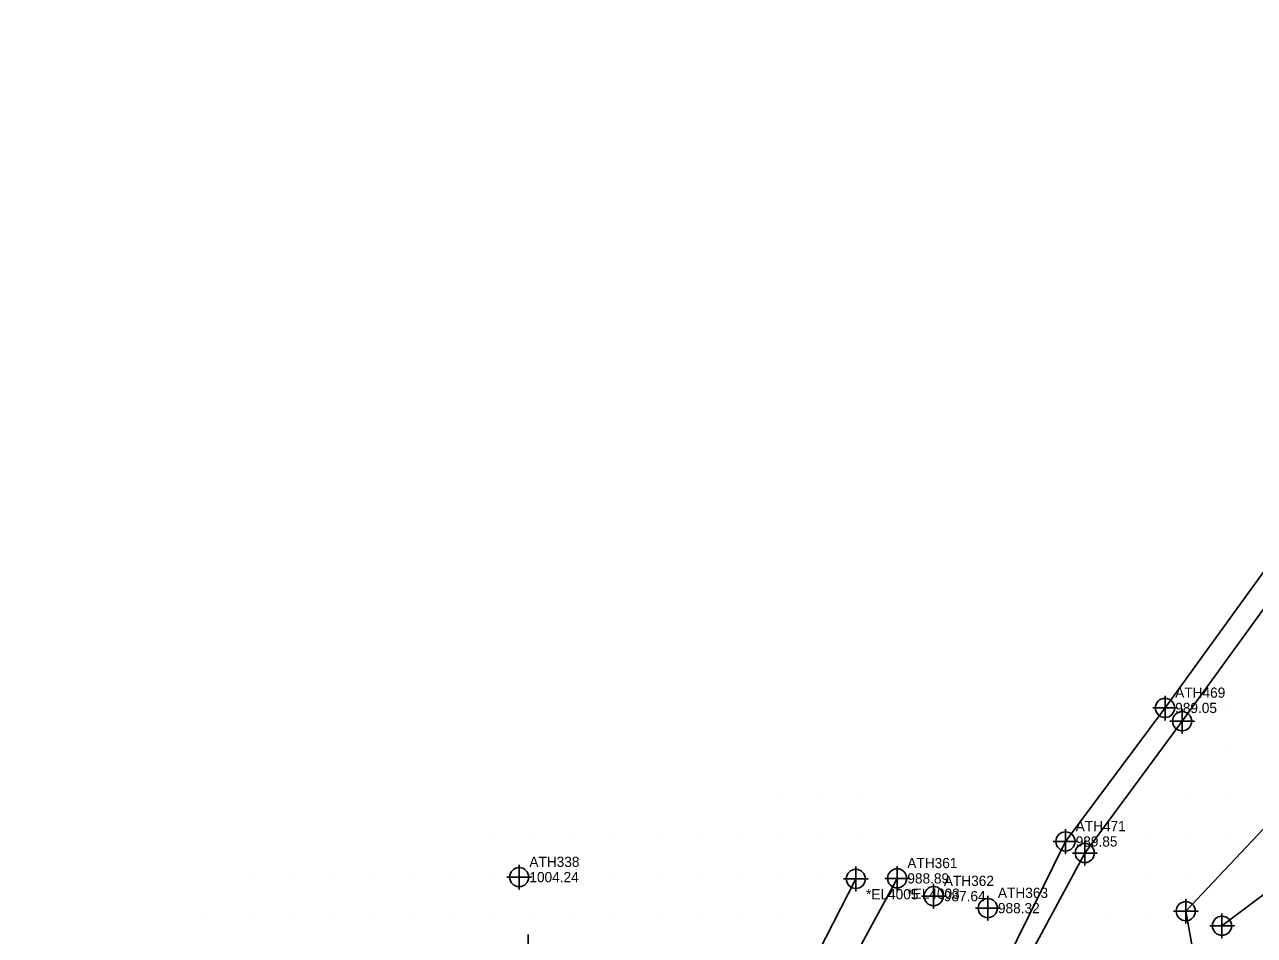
# Model space of a CAD drawing. Extents: x 1116680 to 1117499, y 661040 to 661703.
# Drawn here: x 1116885.3 to 1117186.4, y 661475 to 661698 of the extents above; entities that cross this region are included whole.
import ezdxf

# ---------------------------------------------------------------- set-up
doc = ezdxf.new("R2010")
doc.units = 0
for name, color, linetype in [('Exist DTM Breakline', 7, 'Continuous'), ('Exist DTM Breakline Cogo Comment', 7, 'Continuous'), ('Exist DTM Breakline Cogo Point CELL', 7, 'Continuous'), ('Exist DTM Crownline', 7, 'Continuous'), ('Exist DTM Drainline Cogo Comment', 7, 'Continuous'), ('Exist DTM Drainline Cogo Elevation', 7, 'Continuous'), ('Exist DTM Drainline Cogo Number', 7, 'Continuous'), ('Exist DTM Drainline Cogo Point CELL', 7, 'Continuous'), ('Exist DTM QL2 LIDAR Elevation Point', 7, 'Continuous'), ('Exist DTM Regular Point CELL', 7, 'Continuous'), ('Exist DTM Regular Point Cogo Elevation', 7, 'Continuous'), ('Exist DTM Regular Point Cogo Number', 7, 'Continuous'), ('Exist DTM Regular Point Underwater CELL', 7, 'Continuous'), ('Exist DTM Regular Point Underwater Cogo Elevation', 7, 'Continuous'), ('Exist DTM Regular Point Underwater Cogo Number', 7, 'Continuous'), ('Exist Hydro Stream or Body of Water', 7, 'Continuous'), ('Exist Roads EOP', 7, 'Continuous')]:
    doc.layers.add(name, color=color, linetype=linetype)

msp = doc.modelspace()

# ---------------------------------------------------------------- linework, layer by layer
at = {"layer": 'Exist DTM Breakline'}
for points in [[(1117128.128, 661464.169), (1117144.878, 661495.181), (1117168.704, 661527.446), (1117200.502, 661571.22), (1117217.144, 661612.812), (1117257.559, 661667.144), (1117273.855, 661694.87)], [(1117194.27, 661465.73), (1117171.77, 661469.09), (1117169.6, 661480.945), (1117189.888, 661502.41), (1117205.863, 661515.329), (1117217.572, 661523.34), (1117225.692, 661514.312), (1117221.27, 661493.665), (1117211.404, 661481.256)], [(1117178.472, 661477.376), (1117196.976, 661491.194), (1117215.079, 661507.353)], [(1117038.555, 661379.021), (1117059.605, 661420.588), (1117070.329, 661452.789), (1117088.813, 661488.846)]]:
    msp.add_lwpolyline(points, dxfattribs=at)
at = {"layer": 'Exist DTM Breakline Cogo Point CELL'}
for points in [[(1117168.704, 661530.446), (1117168.704, 661524.446), (1117168.704, 661527.446), (1117171.704, 661527.446), (1117165.704, 661527.446)], [(1117144.878, 661498.181), (1117144.878, 661492.181), (1117144.878, 661495.181), (1117147.878, 661495.181), (1117141.878, 661495.181)], [(1117088.813, 661491.846), (1117088.813, 661485.846), (1117088.813, 661488.846), (1117091.813, 661488.846), (1117085.813, 661488.846)], [(1117169.6, 661483.945), (1117169.6, 661477.945), (1117169.6, 661480.945), (1117172.6, 661480.945), (1117166.6, 661480.945)], [(1117178.472, 661480.376), (1117178.472, 661474.376), (1117178.472, 661477.376), (1117181.472, 661477.376), (1117175.472, 661477.376)], [(1117008.611, 661475.228), (1117008.611, 661469.228), (1117008.611, 661472.228), (1117011.611, 661472.228), (1117005.611, 661472.228)]]:
    msp.add_lwpolyline(points, dxfattribs=at)
for centre in [(1117168.704, 661527.446), (1117144.878, 661495.181), (1117088.813, 661488.846), (1117169.6, 661480.945), (1117178.472, 661477.376)]:
    msp.add_circle(centre, 2.344, dxfattribs=at)
at = {"layer": 'Exist DTM Crownline'}
msp.add_spline([(1117128.608, 661382.881), (1117161.083, 661393.544), (1117193.928, 661410.345), (1117229.679, 661438.384), (1117257.918, 661472.931), (1117285.234, 661525.056), (1117305.735, 661573.245), (1117329.129, 661633.315)], degree=3, dxfattribs=at)
at = {"layer": 'Exist DTM Drainline Cogo Point CELL'}
for points in [[(1117164.523, 661533.702), (1117164.523, 661527.702), (1117164.523, 661530.702), (1117167.523, 661530.702), (1117161.523, 661530.702)], [(1117140.152, 661501.019), (1117140.152, 661495.019), (1117140.152, 661498.019), (1117143.152, 661498.019), (1117137.152, 661498.019)], [(1117098.924, 661491.98), (1117098.924, 661485.98), (1117098.924, 661488.98), (1117101.924, 661488.98), (1117095.924, 661488.98)]]:
    msp.add_lwpolyline(points, dxfattribs=at)
for centre in [(1117164.523, 661530.702), (1117140.152, 661498.019), (1117098.924, 661488.98)]:
    msp.add_circle(centre, 2.344, dxfattribs=at)
at = {"layer": 'Exist DTM QL2 LIDAR Elevation Point'}
for p, q in [((1117180, 661530), (1117180, 661530)), ((1117180, 661520), (1117180, 661520)), ((1117070, 661510), (1117070, 661510)), ((1117080, 661510), (1117080, 661510)), ((1117090, 661510), (1117090, 661510)), ((1117170, 661510), (1117170, 661510)), ((1117180, 661510), (1117180, 661510)), ((1117000, 661500), (1117000, 661500)), ((1117010, 661500), (1117010, 661500)), ((1117020, 661500), (1117020, 661500)), ((1117030, 661500), (1117030, 661500)), ((1117040, 661500), (1117040, 661500)), ((1117050, 661500), (1117050, 661500)), ((1117060, 661500), (1117060, 661500)), ((1117070, 661500), (1117070, 661500)), ((1117080, 661500), (1117080, 661500)), ((1117090, 661500), (1117090, 661500)), ((1117160, 661500), (1117160, 661500)), ((1117170, 661500), (1117170, 661500)), ((1117180, 661500), (1117180, 661500)), ((1116940, 661490), (1116940, 661490)), ((1116950, 661490), (1116950, 661490)), ((1116960, 661490), (1116960, 661490)), ((1116970, 661490), (1116970, 661490)), ((1116980, 661490), (1116980, 661490)), ((1116990, 661490), (1116990, 661490)), ((1117000, 661490), (1117000, 661490)), ((1117010, 661490), (1117010, 661490)), ((1117020, 661490), (1117020, 661490)), ((1117030, 661490), (1117030, 661490)), ((1117040, 661490), (1117040, 661490)), ((1117050, 661490), (1117050, 661490)), ((1117060, 661490), (1117060, 661490)), ((1117070, 661490), (1117070, 661490)), ((1117080, 661490), (1117080, 661490)), ((1117160, 661490), (1117160, 661490)), ((1117170, 661490), (1117170, 661490)), ((1116930, 661480), (1116930, 661480)), ((1116940, 661480), (1116940, 661480)), ((1116950, 661480), (1116950, 661480)), ((1116960, 661480), (1116960, 661480)), ((1116970, 661480), (1116970, 661480)), ((1116980, 661480), (1116980, 661480)), ((1116990, 661480), (1116990, 661480)), ((1117000, 661480), (1117000, 661480)), ((1117010, 661480), (1117010, 661480)), ((1117020, 661480), (1117020, 661480)), ((1117030, 661480), (1117030, 661480)), ((1117040, 661480), (1117040, 661480)), ((1117050, 661480), (1117050, 661480)), ((1117060, 661480), (1117060, 661480)), ((1117070, 661480), (1117070, 661480)), ((1117150, 661480), (1117150, 661480)), ((1117160, 661480), (1117160, 661480))]:
    msp.add_line(p, q, dxfattribs=at)
at = {"layer": 'Exist DTM Regular Point CELL'}
msp.add_lwpolyline([(1117006.371, 661492.281), (1117006.371, 661486.281), (1117006.371, 661489.281), (1117009.371, 661489.281), (1117003.371, 661489.281)], dxfattribs=at)
msp.add_circle((1117006.371, 661489.281), 2.344, dxfattribs=at)
at = {"layer": 'Exist DTM Regular Point Underwater CELL'}
for points in [[(1117107.864, 661487.626), (1117107.864, 661481.626), (1117107.864, 661484.626), (1117110.864, 661484.626), (1117104.864, 661484.626)], [(1117121.112, 661484.694), (1117121.112, 661478.694), (1117121.112, 661481.694), (1117124.112, 661481.694), (1117118.112, 661481.694)]]:
    msp.add_lwpolyline(points, dxfattribs=at)
for centre in [(1117107.864, 661484.626), (1117121.112, 661481.694)]:
    msp.add_circle(centre, 2.344, dxfattribs=at)
at = {"layer": 'Exist Hydro Stream or Body of Water'}
for points in [[(1117125.362, 661468.034), (1117140.152, 661498.019), (1117164.523, 661530.702), (1117196.253, 661574.433), (1117208.146, 661610.151), (1117250.567, 661671.867), (1117271.101, 661697.995)], [(1116885.259, 661065.084), (1116909.522, 661128.826), (1116941.429, 661187.261), (1116973.299, 661231.015), (1117008.806, 661288.675), (1117028.625, 661329.39), (1117037.259, 661346.044), (1117054.084, 661350.959), (1117065.864, 661380.085), (1117058.435, 661381.413), (1117066.561, 661417.266), (1117077.352, 661449.252), (1117098.924, 661488.98)]]:
    msp.add_lwpolyline(points, dxfattribs=at)
at = {"layer": 'Exist Roads EOP'}
for points in [[(1117102.286, 661387.333), (1117126.621, 661394.057), (1117156.418, 661404.979), (1117187.204, 661421.689), (1117219.891, 661448.41), (1117247.012, 661480.823), (1117275.546, 661531.18), (1117296.661, 661577.27), (1117320.803, 661635.676)], [(1117131.334, 661372.856), (1117166.321, 661382.847), (1117200.815, 661399.841), (1117238.067, 661430.322), (1117267.048, 661465.689), (1117295.472, 661519.132), (1117314.821, 661568.418)]]:
    msp.add_spline(points, degree=3, dxfattribs=at)

# ---------------------------------------------------------------- texts
at = {"layer": 'Exist DTM Breakline Cogo Comment'}
msp.add_text('*EL4005', height=2.5, dxfattribs=at).set_placement((1117091.313, 661483.846))
at = {"layer": 'Exist DTM Drainline Cogo Comment'}
msp.add_text('*EL4003', height=2.5, dxfattribs=at).set_placement((1117101.424, 661483.98))
at = {"layer": 'Exist DTM Drainline Cogo Elevation'}
for s, p in [('989.05', (1117167.023, 661529.452)), ('989.85', (1117142.652, 661496.769)), ('988.89', (1117101.424, 661487.73))]:
    msp.add_text(s, height=2.5, dxfattribs=at).set_placement(p)
at = {"layer": 'Exist DTM Drainline Cogo Number'}
for s, p in [('ATH469', (1117167.023, 661533.202)), ('ATH471', (1117142.652, 661500.519)), ('ATH361', (1117101.424, 661491.48))]:
    msp.add_text(s, height=2.5, dxfattribs=at).set_placement(p)
at = {"layer": 'Exist DTM Regular Point Cogo Elevation'}
msp.add_text('1004.24', height=2.5, dxfattribs=at).set_placement((1117008.871, 661488.031))
at = {"layer": 'Exist DTM Regular Point Cogo Number'}
msp.add_text('ATH338', height=2.5, dxfattribs=at).set_placement((1117008.871, 661491.781))
at = {"layer": 'Exist DTM Regular Point Underwater Cogo Elevation'}
for s, p in [('987.64', (1117110.364, 661483.376)), ('988.32', (1117123.612, 661480.444))]:
    msp.add_text(s, height=2.5, dxfattribs=at).set_placement(p)
at = {"layer": 'Exist DTM Regular Point Underwater Cogo Number'}
for s, p in [('ATH362', (1117110.364, 661487.126)), ('ATH363', (1117123.612, 661484.194))]:
    msp.add_text(s, height=2.5, dxfattribs=at).set_placement(p)

doc.saveas('drawing.dxf')
